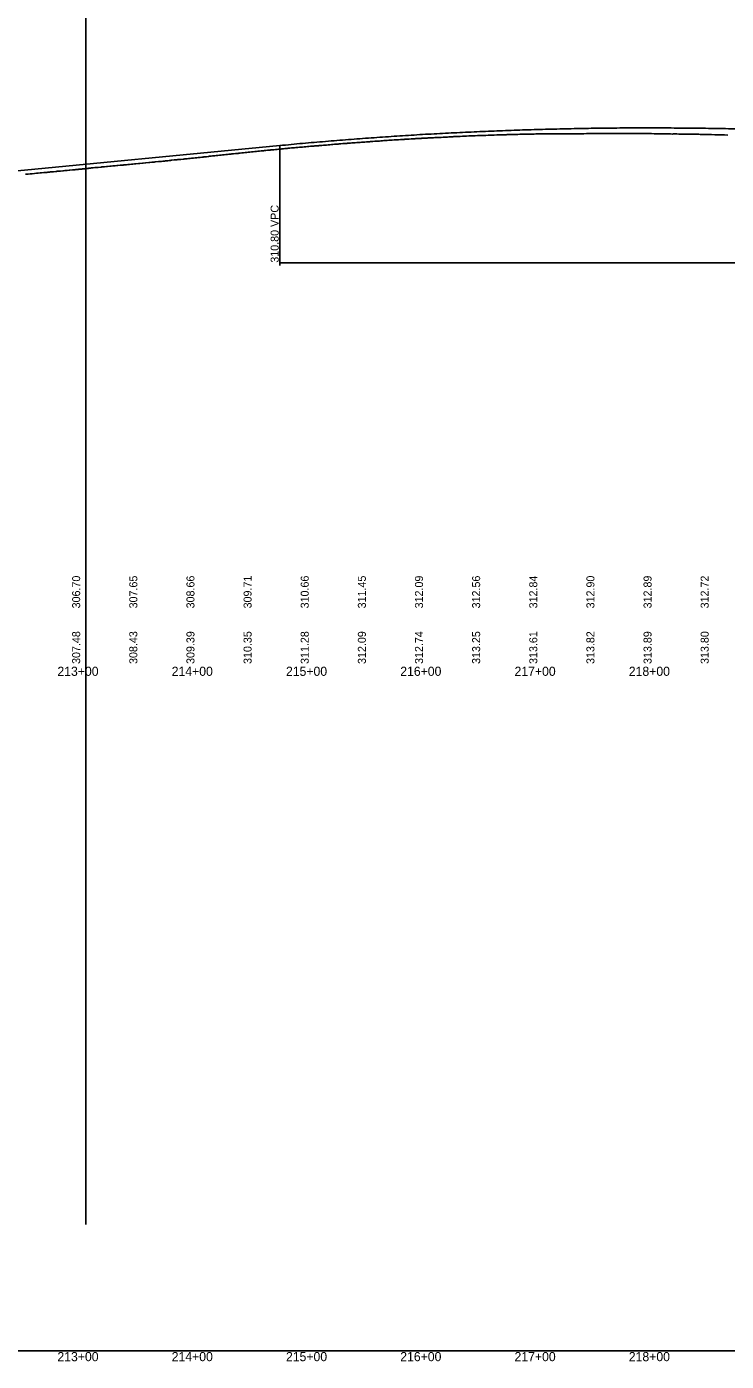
# Model space of a CAD drawing. Extents: x 1838386 to 1955906, y 719739 to 834437.
# Drawn here: x 1898615 to 1899228, y 825624 to 826791 of the extents above; entities that cross this region are included whole.
import ezdxf

# ---------------------------------------------------------------- set-up
doc = ezdxf.new("R2010")
doc.units = 0
for name, color, linetype in [('RD_DDB_Profile_EX', 7, 'Continuous'), ('RD_DDB_Profile_PR', 7, 'Continuous'), ('RD_DDB_StaTX', 7, 'Continuous'), ('RD_DDB_StripGrade', 7, 'Continuous'), ('RD_DDB_VCLbl', 7, 'Continuous'), ('RD_GPK_Profile_Cell', 7, 'Continuous'), ('RD_Sketch1', 7, 'Continuous')]:
    doc.layers.add(name, color=color, linetype=linetype)

msp = doc.modelspace()

# ---------------------------------------------------------------- linework, layer by layer
at = {"layer": 'RD_DDB_Profile_EX'}
for points in [[(1898790.9, 826679.3), (1898792.3, 826679.5), (1898792.8, 826679.6), (1898793.9, 826679.7), (1898794.7, 826679.8), (1898795.1, 826679.8), (1898796.4, 826679.9), (1898798, 826680.1), (1898798.4, 826680.1), (1898799.5, 826680.3), (1898800.4, 826680.3), (1898800.8, 826680.4), (1898802, 826680.5), (1898803.6, 826680.7), (1898805.1, 826680.9), (1898806.4, 826681), (1898807.8, 826681.1), (1898809.2, 826681.3), (1898810.7, 826681.4), (1898812, 826681.6), (1898813.4, 826681.7), (1898814.8, 826681.8), (1898815.3, 826681.9), (1898816.3, 826682), (1898817.6, 826682.1), (1898818.9, 826682.3), (1898820.4, 826682.4), (1898820.8, 826682.5), (1898821.9, 826682.6), (1898822.7, 826682.6), (1898823.1, 826682.7), (1898824.5, 826682.8), (1898826, 826683), (1898827.4, 826683.1), (1898828.3, 826683.2), (1898828.8, 826683.3), (1898830.2, 826683.4), (1898831.5, 826683.5), (1898833, 826683.7), (1898834.4, 826683.8), (1898835.7, 826683.9), (1898837.1, 826684.1), (1898837.7, 826684.1), (1898838.6, 826684.2), (1898839.9, 826684.3), (1898841.3, 826684.4), (1898842.7, 826684.6), (1898843.2, 826684.6), (1898844.2, 826684.7), (1898845.1, 826684.8), (1898845.5, 826684.8), (1898846.9, 826685), (1898848.3, 826685.1), (1898849.7, 826685.2), (1898850.7, 826685.3), (1898851.1, 826685.3), (1898852.5, 826685.5), (1898853.9, 826685.6), (1898855.2, 826685.7), (1898856.7, 826685.8), (1898858.1, 826685.9), (1898859.5, 826686.1), (1898860.9, 826686.2), (1898862.3, 826686.3), (1898863.8, 826686.5), (1898865.1, 826686.6), (1898865.6, 826686.6), (1898866.5, 826686.7), (1898867.5, 826686.8), (1898867.9, 826686.8), (1898869.4, 826686.9), (1898870.7, 826687), (1898871.1, 826687.1), (1898872, 826687.2), (1898873, 826687.2), (1898873.5, 826687.3), (1898874.9, 826687.4), (1898876.3, 826687.5), (1898877.6, 826687.6), (1898879.1, 826687.7), (1898880.5, 826687.8), (1898881.9, 826688), (1898883.2, 826688.1), (1898884.7, 826688.2), (1898886.2, 826688.3), (1898887.5, 826688.4), (1898887.9, 826688.4), (1898888.8, 826688.5), (1898889.8, 826688.6), (1898890.3, 826688.6), (1898891.9, 826688.8), (1898893.1, 826688.9), (1898893.5, 826688.9), (1898894.3, 826689), (1898895.4, 826689), (1898895.9, 826689.1), (1898897.4, 826689.2), (1898898.7, 826689.3), (1898899.8, 826689.4), (1898901.5, 826689.5), (1898902.8, 826689.6)], [(1898902.8, 826689.6), (1898904.3, 826689.7), (1898905.5, 826689.8), (1898907.1, 826689.9), (1898908.4, 826690), (1898909.9, 826690.1), (1898910.3, 826690.2), (1898911.1, 826690.2), (1898912.7, 826690.3), (1898914.3, 826690.5), (1898915.5, 826690.5), (1898915.8, 826690.6), (1898916.6, 826690.6), (1898917.7, 826690.7), (1898918.3, 826690.7), (1898919.9, 826690.9), (1898921.1, 826690.9), (1898922.2, 826691), (1898923.9, 826691.1), (1898925.2, 826691.2), (1898926.6, 826691.3), (1898927.8, 826691.4), (1898929.5, 826691.5), (1898930.7, 826691.6), (1898932.2, 826691.7), (1898932.6, 826691.7), (1898933.4, 826691.8), (1898935, 826691.9), (1898936.8, 826692), (1898937.8, 826692.1), (1898938.2, 826692.1), (1898938.9, 826692.1), (1898940.1, 826692.2), (1898940.6, 826692.2), (1898942.4, 826692.4), (1898943.4, 826692.4), (1898944.4, 826692.5), (1898945.6, 826692.5), (1898946.2, 826692.6), (1898947.5, 826692.7), (1898949, 826692.8), (1898950.1, 826692.8), (1898951.8, 826692.9), (1898953.1, 826693), (1898954.6, 826693.1), (1898955, 826693.1), (1898955.7, 826693.2), (1898957.4, 826693.3), (1898959.2, 826693.4), (1898960.2, 826693.4), (1898960.5, 826693.4), (1898961.2, 826693.5), (1898962.5, 826693.5), (1898963, 826693.6), (1898964.8, 826693.7), (1898965.8, 826693.7), (1898966.7, 826693.8), (1898968, 826693.8), (1898968.6, 826693.9), (1898969.9, 826693.9), (1898971.4, 826694), (1898972.4, 826694.1), (1898974.2, 826694.1), (1898975.4, 826694.2), (1898977, 826694.3), (1898977.4, 826694.3), (1898978, 826694.3), (1898979.8, 826694.4), (1898981.7, 826694.5), (1898982.9, 826694.6), (1898983.5, 826694.6), (1898984.8, 826694.7), (1898985.4, 826694.7), (1898987.3, 826694.8), (1898988.2, 826694.8), (1898989, 826694.9), (1898990.3, 826694.9), (1898991, 826695), (1898992.3, 826695), (1898993.8, 826695.1), (1898994.7, 826695.1), (1898996.6, 826695.2), (1898997.8, 826695.2), (1898999.4, 826695.3), (1898999.7, 826695.3), (1899000.3, 826695.4), (1899002.2, 826695.5), (1899004.1, 826695.5), (1899005.2, 826695.6), (1899005.8, 826695.6), (1899007.2, 826695.6), (1899007.8, 826695.7), (1899009.7, 826695.8), (1899010.6, 826695.8), (1899011.3, 826695.8), (1899012.7, 826695.9), (1899013.4, 826695.9), (1899014.6, 826695.9), (1899016.1, 826696), (1899017, 826696), (1899019, 826696.1)], [(1899019, 826696.1), (1899020.1, 826696.1), (1899021.7, 826696.2), (1899022.1, 826696.2), (1899022.6, 826696.2), (1899024.5, 826696.3), (1899026.6, 826696.4), (1899027.6, 826696.4), (1899028.1, 826696.4), (1899029.5, 826696.5), (1899030.1, 826696.5), (1899032.2, 826696.6), (1899032.9, 826696.6), (1899033.7, 826696.6), (1899035, 826696.6), (1899035.7, 826696.7), (1899037, 826696.7), (1899038.5, 826696.7), (1899039.3, 826696.8), (1899041.3, 826696.8), (1899042.5, 826696.8), (1899044.4, 826696.9), (1899045, 826696.9), (1899046.9, 826697), (1899049, 826697), (1899049.9, 826697), (1899050.4, 826697.1), (1899051.9, 826697.1), (1899052.5, 826697.1), (1899054.7, 826697.1), (1899055.3, 826697.1), (1899055.9, 826697.2), (1899057.4, 826697.2), (1899058.1, 826697.2), (1899059.3, 826697.2), (1899060.9, 826697.3), (1899061.6, 826697.3), (1899063.7, 826697.3), (1899064.9, 826697.3), (1899066.5, 826697.3), (1899067.2, 826697.4), (1899069.3, 826697.4), (1899070.4, 826697.4), (1899072.3, 826697.4), (1899072.8, 826697.4), (1899074.9, 826697.4), (1899077.1, 826697.5), (1899077.9, 826697.5), (1899078.3, 826697.5), (1899079.8, 826697.4), (1899080.5, 826697.4), (1899082.7, 826697.4), (1899083.3, 826697.4), (1899083.8, 826697.4), (1899085.3, 826697.4), (1899086.1, 826697.4), (1899087.2, 826697.4), (1899088.9, 826697.5), (1899089.4, 826697.5), (1899090.9, 826697.4), (1899091.7, 826697.5), (1899092.8, 826697.5), (1899094.5, 826697.5), (1899095.1, 826697.5), (1899097.3, 826697.5), (1899098.4, 826697.5), (1899100.3, 826697.5), (1899100.7, 826697.5), (1899102.9, 826697.5), (1899105.1, 826697.6), (1899105.8, 826697.6), (1899106.2, 826697.6), (1899107.7, 826697.6), (1899108.4, 826697.6), (1899110.8, 826697.6), (1899111.7, 826697.6), (1899113.3, 826697.6), (1899114, 826697.6), (1899116.4, 826697.7), (1899116.8, 826697.7), (1899117.3, 826697.7), (1899118.8, 826697.6), (1899119.6, 826697.7), (1899120.8, 826697.6), (1899122.4, 826697.7), (1899122.9, 826697.7), (1899125.2, 826697.7), (1899126.3, 826697.7), (1899128, 826697.7), (1899128.6, 826697.7), (1899130.8, 826697.7), (1899131.9, 826697.7), (1899133.8, 826697.7), (1899134.1, 826697.7), (1899136.4, 826697.7), (1899138.8, 826697.7), (1899139.6, 826697.7), (1899141.2, 826697.7), (1899142, 826697.7), (1899144.5, 826697.7), (1899145.1, 826697.7)], [(1899145.1, 826697.7), (1899146.8, 826697.7), (1899147.6, 826697.7), (1899150, 826697.7), (1899150.4, 826697.7), (1899150.8, 826697.7), (1899153.2, 826697.7), (1899154.3, 826697.7), (1899156, 826697.7), (1899156.4, 826697.7), (1899158.8, 826697.6), (1899159.8, 826697.6), (1899161.6, 826697.6), (1899162, 826697.6), (1899164.4, 826697.5), (1899165.4, 826697.5), (1899167.5, 826697.5), (1899170, 826697.4), (1899173, 826697.4), (1899174.8, 826697.3), (1899175.6, 826697.3), (1899178.6, 826697.3), (1899180.3, 826697.2), (1899181.2, 826697.3), (1899184.2, 826697.3), (1899185.9, 826697.2), (1899186.8, 826697.2), (1899187.8, 826697.2), (1899189.8, 826697.2), (1899192.4, 826697.1), (1899193.4, 826697.1), (1899195.1, 826697.1), (1899195.5, 826697.1), (1899198, 826697.1), (1899198.9, 826697), (1899200.7, 826697), (1899201.1, 826697), (1899203.6, 826697), (1899204.5, 826696.9), (1899206.6, 826696.9), (1899209.1, 826696.8), (1899212, 826696.8), (1899213.9, 826696.7), (1899214.7, 826696.7), (1899217.6, 826696.6), (1899219.5, 826696.6), (1899220.3, 826696.5), (1899223.2, 826696.5), (1899225, 826696.4), (1899225.9, 826696.4), (1899228.8, 826696.3)], [(1898669.2, 826667.2), (1898669.8, 826667.3), (1898671.2, 826667.4), (1898671.9, 826667.5), (1898673.6, 826667.6), (1898675, 826667.8), (1898677.8, 826668), (1898680.5, 826668.3), (1898681.2, 826668.4), (1898683.3, 826668.6), (1898685, 826668.7), (1898686, 826668.8), (1898688.2, 826669), (1898688.8, 826669.1), (1898689.2, 826669.1), (1898690.7, 826669.3), (1898691.6, 826669.4), (1898692.6, 826669.5), (1898694.2, 826669.6), (1898695.2, 826669.7), (1898697.1, 826669.9), (1898698.6, 826670), (1898699.8, 826670.1), (1898700.2, 826670.2), (1898701.2, 826670.3), (1898702.1, 826670.4), (1898702.6, 826670.4), (1898703.8, 826670.5), (1898705.4, 826670.6), (1898707, 826670.8), (1898708.1, 826670.9), (1898709.7, 826671), (1898710.9, 826671.2), (1898713, 826671.4), (1898713.7, 826671.4), (1898714.4, 826671.5), (1898716.5, 826671.7), (1898717.3, 826671.8), (1898719.3, 826672), (1898719.6, 826672), (1898722.1, 826672.2), (1898723, 826672.3), (1898724.9, 826672.5), (1898726.8, 826672.7), (1898727.7, 826672.8), (1898730.6, 826673.1), (1898732.4, 826673.2), (1898733.3, 826673.3), (1898734.3, 826673.4), (1898735.7, 826673.6), (1898736.1, 826673.6), (1898736.5, 826673.7), (1898738.9, 826673.9), (1898740, 826674), (1898741.2, 826674.1), (1898741.7, 826674.2), (1898742.4, 826674.3), (1898744.5, 826674.5), (1898746.7, 826674.7), (1898747.5, 826674.8), (1898748.1, 826674.8), (1898749.5, 826675), (1898750.1, 826675), (1898752.3, 826675.3), (1898752.9, 826675.3), (1898753.8, 826675.4), (1898755.1, 826675.5), (1898755.7, 826675.6), (1898757, 826675.7), (1898757.8, 826675.8), (1898758.5, 826675.9), (1898759.6, 826676), (1898761.3, 826676.2), (1898762.7, 826676.3), (1898763.3, 826676.4), (1898764.1, 826676.5), (1898765.4, 826676.7), (1898767, 826676.8), (1898768.5, 826677), (1898768.8, 826677), (1898769.8, 826677.1), (1898770.2, 826677.2), (1898771.1, 826677.3), (1898772.1, 826677.4), (1898772.6, 826677.4), (1898774, 826677.6), (1898774.3, 826677.6), (1898775.4, 826677.7), (1898775.8, 826677.8), (1898776.8, 826677.9), (1898777.8, 826678), (1898778.2, 826678), (1898779.9, 826678.2), (1898781, 826678.3), (1898782.5, 826678.5), (1898783.9, 826678.6), (1898785.4, 826678.8), (1898786.7, 826678.9), (1898788.2, 826679.1), (1898789.5, 826679.2), (1898790.9, 826679.3)], [(1898614.4, 826662), (1898615.8, 826662.2), (1898616.5, 826662.2), (1898618.3, 826662.4), (1898619.3, 826662.5), (1898619.8, 826662.5), (1898620.2, 826662.5), (1898622.2, 826662.7), (1898624, 826662.9), (1898624.8, 826663), (1898625.3, 826663), (1898627, 826663.2), (1898627.6, 826663.2), (1898628.3, 826663.3), (1898630.4, 826663.5), (1898630.9, 826663.5), (1898632.1, 826663.6), (1898633.1, 826663.7), (1898633.5, 826663.8), (1898634.5, 826663.9), (1898635.5, 826663.9), (1898635.9, 826664), (1898636.4, 826664), (1898637.4, 826664.1), (1898638.7, 826664.2), (1898640.7, 826664.4), (1898641.4, 826664.5), (1898642, 826664.6), (1898644.2, 826664.8), (1898645, 826664.8), (1898647, 826665), (1898647.4, 826665.1), (1898648.8, 826665.2), (1898649.7, 826665.3), (1898650.7, 826665.4), (1898652.5, 826665.6), (1898653, 826665.6), (1898655.3, 826665.8), (1898657.3, 826666), (1898658.4, 826666.1), (1898659, 826666.2), (1898660.3, 826666.3), (1898660.8, 826666.4), (1898662.2, 826666.5), (1898663.6, 826666.6), (1898664, 826666.7), (1898665.2, 826666.8), (1898666.4, 826666.9), (1898667.5, 826667), (1898669.2, 826667.2)]]:
    msp.add_lwpolyline(points, dxfattribs=at)
at = {"layer": 'RD_DDB_Profile_PR'}
msp.add_line((1898396.7, 826645), (1898836.8, 826687.1), dxfattribs=at)
msp.add_spline([(1898836.8, 826687.1), (1898856.8, 826689), (1898876.8, 826690.7), (1898896.8, 826692.3), (1898916.8, 826693.8), (1898936.8, 826695.2), (1898956.8, 826696.5), (1898976.8, 826697.6), (1898996.8, 826698.6), (1899016.8, 826699.5), (1899036.8, 826700.3), (1899056.8, 826701), (1899076.8, 826701.5), (1899096.8, 826702), (1899116.8, 826702.3), (1899136.8, 826702.5), (1899156.8, 826702.5), (1899176.8, 826702.5), (1899196.8, 826702.3), (1899216.8, 826702.1), (1899236.8, 826701.7), (1899256.8, 826701.2), (1899276.8, 826700.5), (1899296.8, 826699.8), (1899316.8, 826698.9), (1899336.8, 826697.9), (1899356.8, 826696.8), (1899376.8, 826695.6), (1899396.8, 826694.2), (1899416.8, 826692.8), (1899436.8, 826691.2), (1899456.8, 826689.5), (1899476.8, 826687.7), (1899496.8, 826685.7), (1899516.8, 826683.7), (1899536.8, 826681.5), (1899556.8, 826679.2), (1899576.8, 826676.8), (1899596.8, 826674.3), (1899616.8, 826671.6), (1899636.8, 826668.8), (1899656.8, 826666), (1899676.8, 826663), (1899696.8, 826659.8), (1899716.8, 826656.6), (1899736.8, 826653.2), (1899756.8, 826649.8), (1899776.8, 826646.2), (1899796.8, 826642.4), (1899816.8, 826638.6), (1899836.8, 826634.7)], degree=3, dxfattribs=at)
at = {"layer": 'RD_DDB_VCLbl'}
for p, q in [((1898836.8, 826582.2), (1898836.8, 826687.1)), ((1898836.8, 826584.7), (1899836.8, 826584.7))]:
    msp.add_line(p, q, dxfattribs=at)
at = {"layer": 'RD_GPK_Profile_Cell'}
msp.add_line((1878363.1, 825633.1), (1904963.1, 825633.1), dxfattribs=at)
at = {"layer": 'RD_Sketch1'}
msp.add_line((1898667.1, 825743.6), (1898667.1, 827268.6), dxfattribs=at)

# ---------------------------------------------------------------- texts
at = {"layer": 'RD_DDB_StaTX'}
for s, p in [('213+00', (1898642.2, 826223.4)), ('214+00', (1898742.2, 826223.4)), ('215+00', (1898842.2, 826223.4)), ('216+00', (1898942.2, 826223.4)), ('217+00', (1899042.2, 826223.4)), ('218+00', (1899142.2, 826223.4)), ('213+00', (1898642.2, 825624.1)), ('214+00', (1898742.2, 825624.1)), ('215+00', (1898842.2, 825624.1)), ('216+00', (1898942.2, 825624.1)), ('217+00', (1899042.2, 825624.1)), ('218+00', (1899142.2, 825624.1))]:
    msp.add_text(s, height=8, dxfattribs=at).set_placement(p)
at = {"layer": 'RD_DDB_StripGrade'}
for s, p in [('310.80 VPC', (1898835.8, 826584.7)), ('306.70', (1898662.1, 826282.4)), ('307.65', (1898712.1, 826282.4)), ('308.66', (1898762.1, 826282.4)), ('309.71', (1898812.1, 826282.4)), ('310.66', (1898862.1, 826282.4)), ('311.45', (1898912.1, 826282.4)), ('312.09', (1898962.1, 826282.4)), ('312.56', (1899012.1, 826282.4)), ('312.84', (1899062.1, 826282.4)), ('312.90', (1899112.1, 826282.4)), ('312.89', (1899162.1, 826282.4)), ('312.72', (1899212.1, 826282.4)), ('307.48', (1898662.1, 826233.8)), ('308.43', (1898712.1, 826233.8)), ('309.39', (1898762.1, 826233.8)), ('310.35', (1898812.1, 826233.8)), ('311.28', (1898862.1, 826233.8)), ('312.09', (1898912.1, 826233.8)), ('312.74', (1898962.1, 826233.8)), ('313.25', (1899012.1, 826233.8)), ('313.61', (1899062.1, 826233.8)), ('313.82', (1899112.1, 826233.8)), ('313.89', (1899162.1, 826233.8)), ('313.80', (1899212.1, 826233.8))]:
    msp.add_text(s, height=7, rotation=90, dxfattribs=at).set_placement(p)

doc.saveas('drawing.dxf')
